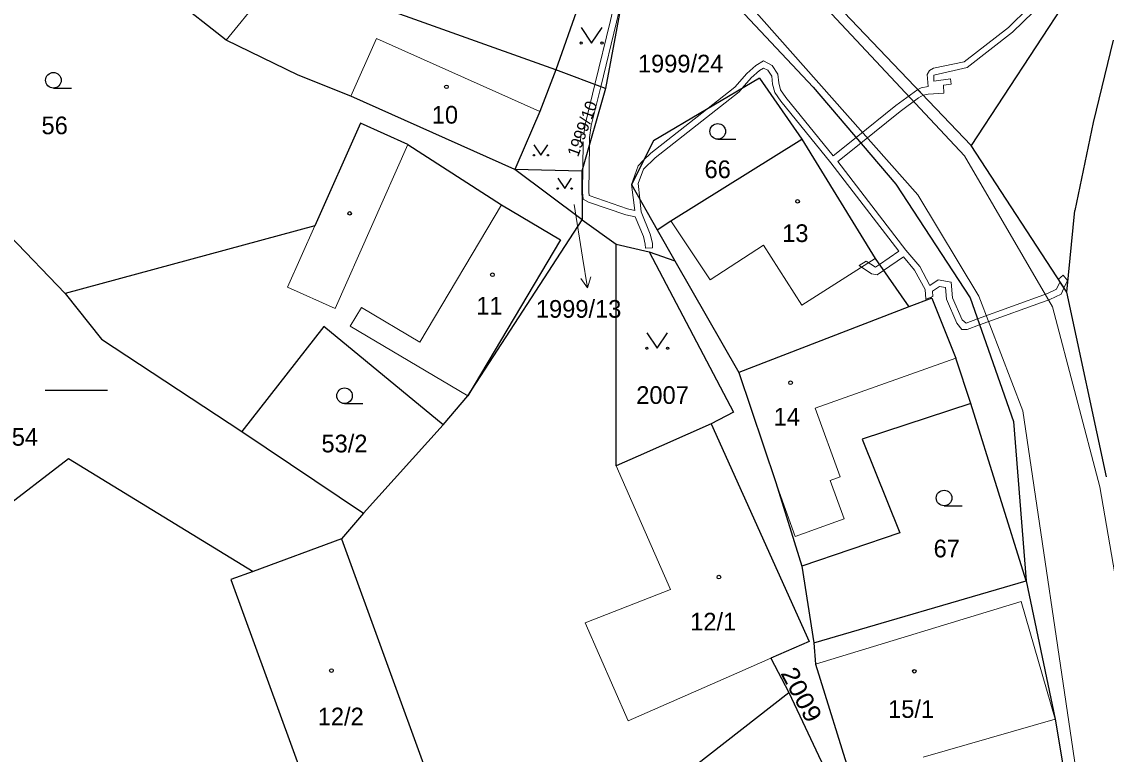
# Model space of a CAD drawing. Extents: x -820420 to -815896, y -1105820 to -1103643.
# Drawn here: x -817759.2 to -817654.9, y -1104849.8 to -1104779.4 of the extents above; entities that cross this region are included whole.
import ezdxf
from ezdxf.enums import TextEntityAlignment as Align

# ---------------------------------------------------------------- set-up
doc = ezdxf.new("R2010")
doc.units = 0
doc.header["$LTSCALE"] = 0.68
for name, color, linetype, lineweight in [('1', 7, 'Continuous', 25), ('13', 7, 'Continuous', 13), ('3', 7, 'Continuous', 25), ('4', 7, 'Continuous', 13), ('5', 7, 'Continuous', 25), ('7', 7, 'Continuous', 13)]:
    doc.layers.add(name, color=color, linetype=linetype, lineweight=lineweight)
doc.layers.add('2', color=7, linetype='Continuous')

msp = doc.modelspace()

# ---------------------------------------------------------------- linework, layer by layer
at = {"layer": '1'}
for p, q in [((-817699.1, -1104768.69), (-817683.11, -1104785.72)), ((-817688.54, -1104769.71), (-817667.93, -1104791.31)), ((-817654.11, -1104770.24), (-817667.93, -1104791.31)), ((-817700.76, -1104773.29), (-817703.09, -1104785.84)), ((-817707.86, -1104784.06), (-817734.21, -1104774.62)), ((-817739.58, -1104781.19), (-817745.74, -1104776.34)), ((-817705.74, -1104777.96), (-817707.86, -1104784.06)), ((-817732.66, -1104784.55), (-817739.58, -1104781.19)), ((-817654.26, -1104781.19), (-817656.2, -1104789.12)), ((-817727.59, -1104786.57), (-817732.66, -1104784.55)), ((-817707.86, -1104784.06), (-817709.4, -1104788.04)), ((-817703.09, -1104785.84), (-817707.86, -1104784.06)), ((-817688.29, -1104784.84), (-817698.49, -1104790.88)), ((-817688.29, -1104784.84), (-817684.2, -1104790.71)), ((-817703.09, -1104785.84), (-817705.37, -1104793.78)), ((-817683.11, -1104785.72), (-817675.19, -1104795.04)), ((-817711.8, -1104793.61), (-817727.59, -1104786.57)), ((-817709.4, -1104788.04), (-817711.62, -1104793.19)), ((-817726.65, -1104789.18), (-817731.05, -1104799.04)), ((-817722.09, -1104791.21), (-817726.65, -1104789.18)), ((-817656.2, -1104789.12), (-817657.97, -1104797.56)), ((-817722.09, -1104791.21), (-817713.09, -1104797.01)), ((-817698.49, -1104790.88), (-817700.61, -1104795.06)), ((-817696.82, -1104798.57), (-817684.2, -1104790.71)), ((-817684.2, -1104790.71), (-817677.17, -1104802.17)), ((-817658.74, -1104805.43), (-817667.93, -1104791.31)), ((-817711.62, -1104793.19), (-817711.8, -1104793.61)), ((-817705.37, -1104793.78), (-817711.8, -1104793.61)), ((-817705.35, -1104798.45), (-817711.8, -1104793.61)), ((-817705.37, -1104793.78), (-817705.35, -1104798.45)), ((-817700.61, -1104795.06), (-817698.12, -1104799.42)), ((-817675.19, -1104795.04), (-817668.03, -1104805.97)), ((-817713.09, -1104797.01), (-817707.42, -1104800.38)), ((-817658.74, -1104805.43), (-817657.97, -1104797.56)), ((-817716.34, -1104815.39), (-817705.35, -1104798.45)), ((-817705.35, -1104798.45), (-817702.08, -1104800.8)), ((-817698.12, -1104799.42), (-817696.82, -1104798.57)), ((-817731.05, -1104799.04), (-817755.07, -1104805.53)), ((-817698.12, -1104799.42), (-817696.42, -1104802.39)), ((-817760.41, -1104799.96), (-817755.07, -1104805.53)), ((-817707.42, -1104800.38), (-817716.34, -1104815.39)), ((-817702.08, -1104800.8), (-817698.89, -1104801.53)), ((-817702.08, -1104822.11), (-817702.08, -1104800.8)), ((-817698.89, -1104801.53), (-817696.42, -1104802.39)), ((-817698.89, -1104801.53), (-817690.78, -1104816.95)), ((-817696.42, -1104802.39), (-817690.28, -1104813.13)), ((-817677.17, -1104802.17), (-817673.91, -1104806.84)), ((-817755.07, -1104805.53), (-817751.56, -1104809.93)), ((-817654.9, -1104823.17), (-817658.74, -1104805.43)), ((-817673.91, -1104806.84), (-817690.28, -1104813.13)), ((-817671.72, -1104806), (-817673.91, -1104806.84)), ((-817671.72, -1104806), (-817669.41, -1104811.76)), ((-817668.03, -1104805.97), (-817663.86, -1104817.84)), ((-817730.17, -1104808.73), (-817738.07, -1104818.81)), ((-817718.7, -1104818.17), (-817730.17, -1104808.73)), ((-817751.56, -1104809.93), (-817738.07, -1104818.81)), ((-817667.95, -1104816.12), (-817669.41, -1104811.76)), ((-817690.28, -1104813.13), (-817686.73, -1104823.7)), ((-817718.7, -1104818.17), (-817716.34, -1104815.39)), ((-817667.95, -1104816.12), (-817678.41, -1104819.56)), ((-817662.64, -1104833.15), (-817667.95, -1104816.12)), ((-817690.78, -1104816.95), (-817692.93, -1104818.08)), ((-817726.37, -1104826.67), (-817718.7, -1104818.17)), ((-817692.93, -1104818.08), (-817699.95, -1104821.17)), ((-817692.93, -1104818.08), (-817683.51, -1104839)), ((-817663.86, -1104817.84), (-817662.64, -1104833.15)), ((-817738.07, -1104818.81), (-817726.37, -1104826.67)), ((-817678.41, -1104819.56), (-817674.8, -1104828.54)), ((-817763.38, -1104828.05), (-817754.75, -1104821.41)), ((-817754.75, -1104821.41), (-817736.99, -1104832.25)), ((-817699.95, -1104821.17), (-817702.08, -1104822.11)), ((-817686.73, -1104823.7), (-817684.2, -1104831.76)), ((-817726.37, -1104826.67), (-817728.47, -1104829.12)), ((-817674.8, -1104828.54), (-817684.2, -1104831.76)), ((-817728.47, -1104829.12), (-817736.99, -1104832.25)), ((-817728.47, -1104829.12), (-817718.79, -1104855.69)), ((-817736.99, -1104832.25), (-817739.13, -1104833.04)), ((-817739.13, -1104833.04), (-817729.45, -1104859.58)), ((-817683.05, -1104839.12), (-817662.64, -1104833.15)), ((-817662.64, -1104833.15), (-817659.86, -1104846.46)), ((-817683.51, -1104839), (-817687.19, -1104840.61)), ((-817687.19, -1104840.61), (-817685.46, -1104843.91)), ((-817682.89, -1104841.18), (-817677.85, -1104857.43)), ((-817698.24, -1104853.82), (-817685.46, -1104843.91)), ((-817685.46, -1104843.91), (-817680.54, -1104854.3)), ((-817659.86, -1104846.46), (-817658.33, -1104855.54))]:
    msp.add_line(p, q, dxfattribs=at)
msp.add_lwpolyline([(-817684.2, -1104831.76), (-817683.05, -1104839.12), (-817682.89, -1104841.18)], dxfattribs=at)
at = {"layer": '13'}
msp.add_lwpolyline([(-817653.28, -1104765.84), (-817654.99, -1104769.48), (-817655.99, -1104770.86), (-817662.37, -1104778.06), (-817664.33, -1104779.97), (-817668.59, -1104783.27), (-817671.54, -1104783.9), (-817671.95, -1104784.1), (-817672.15, -1104784.5), (-817672.08, -1104785.66), (-817672.74, -1104785.79), (-817673.05, -1104785.94), (-817672.54, -1104786.48), (-817672.08, -1104786.38), (-817670.57, -1104786.3), (-817670.59, -1104785.51), (-817669.84, -1104785.42), (-817669.91, -1104784.91), (-817671.51, -1104785.13), (-817671.51, -1104784.56), (-817668.32, -1104783.82), (-817663.95, -1104780.43), (-817661.93, -1104778.48)], dxfattribs=at)
for points in [[(-817701.19, -1104772.34), (-817701.19, -1104773.14), (-817702.62, -1104779.31), (-817704.11, -1104785.46), (-817703.55, -1104785.67), (-817702.04, -1104779.45), (-817701.37, -1104776.55), (-817700.76, -1104773.29)], [(-817687.91, -1104783.19), (-817688.65, -1104783.64), (-817689.52, -1104784.41), (-817690.65, -1104785.72), (-817693.37, -1104787.85), (-817698.73, -1104792.04), (-817699.43, -1104792.74), (-817699.96, -1104793.26), (-817700.61, -1104795.06), (-817700.29, -1104797.55), (-817700.99, -1104797.41), (-817704.67, -1104796.11), (-817704.71, -1104795.77), (-817704.63, -1104791.21), (-817705.27, -1104793.43), (-817705.31, -1104795.81), (-817705.23, -1104796.49), (-817704.74, -1104796.75), (-817701.15, -1104797.99), (-817700.23, -1104798.18), (-817699.45, -1104800.05), (-817699.29, -1104800.79), (-817699.26, -1104801.19), (-817698.56, -1104801.15), (-817698.59, -1104800.69), (-817698.79, -1104799.83), (-817699.68, -1104797.68), (-817699.81, -1104796.46), (-817699.97, -1104794.97), (-817699.44, -1104793.6), (-817698.33, -1104792.5), (-817690.23, -1104786.16), (-817689.94, -1104785.82), (-817689.1, -1104784.83), (-817688.29, -1104784.12), (-817687.89, -1104783.87), (-817687.48, -1104784.08), (-817687.11, -1104784.67), (-817687.04, -1104785.42), (-817686.82, -1104786.22), (-817686.24, -1104787.05), (-817681.43, -1104792.99), (-817674.89, -1104801.47), (-817676.76, -1104802.75), (-817677.14, -1104803.01), (-817678.04, -1104802.44), (-817678.7, -1104802.85), (-817677.52, -1104803.65), (-817676.98, -1104803.75), (-817676.36, -1104803.33), (-817674.45, -1104802.02), (-817673.37, -1104803.29), (-817672.37, -1104805.17), (-817672.3, -1104806.09), (-817671.62, -1104805.84), (-817671.66, -1104805.32), (-817670.97, -1104804.88), (-817670.41, -1104804.98), (-817670.3, -1104806.1), (-817669.32, -1104808.41), (-817668.84, -1104809), (-817668.3, -1104808.99), (-817667.12, -1104808.56), (-817667.32, -1104807.99), (-817668.42, -1104808.39), (-817668.8, -1104808.09), (-817669.72, -1104805.96), (-817669.85, -1104804.46), (-817671.09, -1104804.24), (-817671.91, -1104804.77), (-817672.87, -1104802.95), (-817674.2, -1104801.39), (-817680.76, -1104792.87), (-817678.55, -1104791.09), (-817679, -1104790.55), (-817681.19, -1104792.32), (-817685.76, -1104786.69), (-817686.26, -1104785.96), (-817686.44, -1104785.3), (-817686.53, -1104784.47), (-817687.06, -1104783.62)], [(-817705.27, -1104793.43), (-817704.63, -1104791.21), (-817704.62, -1104790.56), (-817704.46, -1104789.41), (-817703.55, -1104785.67), (-817704.11, -1104785.46), (-817705.04, -1104789.29), (-817705.18, -1104790.23), (-817705.47, -1104790.28), (-817705.49, -1104791), (-817705.23, -1104790.95)], [(-817679, -1104790.55), (-817678.55, -1104791.09), (-817674.77, -1104788.04), (-817672.99, -1104786.75), (-817672.54, -1104786.48), (-817673.05, -1104785.94), (-817675.19, -1104787.48)], [(-817659.54, -1104804.16), (-817659.39, -1104804.44), (-817659.01, -1104805.02), (-817658.66, -1104804.3), (-817659.08, -1104803.78)], [(-817667.32, -1104807.99), (-817667.12, -1104808.56), (-817660.35, -1104806.11), (-817659.29, -1104805.6), (-817659.01, -1104805.02), (-817659.39, -1104804.44), (-817659.73, -1104805.14), (-817660.59, -1104805.55)]]:
    msp.add_lwpolyline(points, close=True, dxfattribs=at)
at = {"layer": '3'}
for p, q in [((-817756.193, -1104785.8), (-817754.443, -1104785.8)), ((-817692.303, -1104790.71), (-817690.553, -1104790.71)), ((-817756.979, -1104814.85), (-817750.979, -1104814.85)), ((-817728.193, -1104816.12), (-817726.443, -1104816.12)), ((-817670.533, -1104825.95), (-817668.783, -1104825.95))]:
    msp.add_line(p, q, dxfattribs=at)
for points in [[(-817705.43, -1104779.969), (-817704.43, -1104781.47), (-817703.43, -1104779.969)], [(-817709.98, -1104791.254), (-817709.31, -1104792.26), (-817708.64, -1104791.254)], [(-817707.69, -1104794.454), (-817707.02, -1104795.46), (-817706.35, -1104794.454)], [(-817699.12, -1104809.309), (-817698.12, -1104810.81), (-817697.12, -1104809.309)]]:
    msp.add_lwpolyline(points, dxfattribs=at)
for centre, radius in [((-817705.43, -1104781.4695), 0.1), ((-817703.43, -1104781.4695), 0.1), ((-817756.1929, -1104785.0498), 0.75), ((-817692.3029, -1104789.9598), 0.75), ((-817709.98, -1104792.2596), 0.067), ((-817708.64, -1104792.2596), 0.067), ((-817707.69, -1104795.4596), 0.067), ((-817706.35, -1104795.4596), 0.067), ((-817699.12, -1104810.8095), 0.1), ((-817697.12, -1104810.8095), 0.1), ((-817728.1929, -1104815.3698), 0.75), ((-817670.5329, -1104825.1998), 0.75)]:
    msp.add_circle(centre, radius, dxfattribs=at)
at = {"layer": '4'}
for p, q in [((-817668.58, -1104792.31), (-817690.38, -1104768.99)), ((-817734.21, -1104774.62), (-817739.58, -1104781.19)), ((-817689.35, -1104777.7), (-817673.06, -1104796.05)), ((-817725.13, -1104781.04), (-817727.59, -1104786.57)), ((-817709.4, -1104788.04), (-817725.13, -1104781.04)), ((-817729.1, -1104806.97), (-817722.09, -1104791.21)), ((-817660.11, -1104806.84), (-817668.58, -1104792.31)), ((-817673.06, -1104796.05), (-817667.18, -1104805.79)), ((-817713.09, -1104797.01), (-817720.94, -1104810.23)), ((-817693.04, -1104804.23), (-817696.82, -1104798.57)), ((-817731.05, -1104799.04), (-817733.67, -1104804.93)), ((-817687.91, -1104800.91), (-817693.04, -1104804.23)), ((-817733.67, -1104804.93), (-817729.1, -1104806.97)), ((-817667.18, -1104805.79), (-817662.96, -1104816.82)), ((-817720.94, -1104810.23), (-817726.57, -1104806.88)), ((-817655.55, -1104824.12), (-817660.11, -1104806.84)), ((-817682.94, -1104816.56), (-817669.41, -1104811.76)), ((-817680.54, -1104823.18), (-817682.94, -1104816.56)), ((-817662.96, -1104816.82), (-817657.44, -1104854.16)), ((-817702.08, -1104822.11), (-817696.84, -1104834.01)), ((-817680.54, -1104823.18), (-817681.48, -1104823.52)), ((-817681.48, -1104823.52), (-817680.15, -1104827.19)), ((-817686.73, -1104823.7), (-817684.85, -1104828.89)), ((-817651.2, -1104849.57), (-817655.55, -1104824.12)), ((-817680.15, -1104827.19), (-817684.85, -1104828.89)), ((-817696.84, -1104834.01), (-817705.05, -1104837.2)), ((-817663.12, -1104835.15), (-817682.89, -1104841.18)), ((-817663.12, -1104835.15), (-817659.86, -1104846.46)), ((-817705.05, -1104837.2), (-817700.91, -1104846.63)), ((-817687.19, -1104840.61), (-817690.47, -1104842.05)), ((-817690.47, -1104842.05), (-817700.91, -1104846.63)), ((-817659.86, -1104846.46), (-817672.54, -1104850.1))]:
    msp.add_line(p, q, dxfattribs=at)
for points in [[(-817687.91, -1104800.91), (-817684.22, -1104806.68), (-817677.17, -1104802.17)], [(-817726.57, -1104806.88), (-817727.64, -1104808.68), (-817716.34, -1104815.39)]]:
    msp.add_lwpolyline(points, dxfattribs=at)
at = {"layer": '5'}
for centre in [(-817718.3968, -1104785.6792), (-817684.6268, -1104796.6892), (-817727.6968, -1104797.8392), (-817713.9668, -1104803.7392), (-817685.2968, -1104814.1192), (-817692.1868, -1104832.7992), (-817729.4568, -1104841.7892), (-817673.3968, -1104841.8592)]:
    msp.add_circle(centre, 0.175, dxfattribs=at)
at = {"layer": '7'}
msp.add_line((-817704.831, -1104805.014), (-817704.493, -1104803.947), dxfattribs=at)
msp.add_lwpolyline([(-817706.11, -1104796.98), (-817705.3, -1104802.05), (-817704.831, -1104805.014), (-817705.482, -1104804.103)], dxfattribs=at)

# ---------------------------------------------------------------- texts
at = {"layer": '2'}
for s, p in [('1999/24', (-817695.869, -1104784.295)), ('10', (-817718.539, -1104789.215)), ('56', (-817756.069, -1104790.235)), ('66', (-817692.309, -1104794.455)), ('13', (-817684.839, -1104800.595)), ('11', (-817714.259, -1104807.565)), ('2007', (-817697.61, -1104816.155)), ('14', (-817685.659, -1104818.235)), ('54', (-817758.929, -1104820.175)), ('53/2', (-817728.199, -1104820.815)), ('67', (-817670.279, -1104830.905)), ('12/1', (-817692.739, -1104837.935)), ('12/2', (-817728.559, -1104847.055)), ('15/1', (-817673.709, -1104846.335))]:
    msp.add_text(s, height=1.7, dxfattribs=at).set_placement(p, align=Align.CENTER)
msp.add_text('1999/10', height=1.139, rotation=70, dxfattribs=at).set_placement((-817704.796, -1104789.8973), align=Align.CENTER)
msp.add_text('1999/13', height=1.7, dxfattribs=at).set_placement((-817709.79, -1104807.875))
at = {"layer": '2', "width": 1.1}
msp.add_text('2009', height=1.7, rotation=298, dxfattribs=at).set_placement((-817684.9962, -1104844.4924), align=Align.CENTER)

doc.saveas('drawing.dxf')
